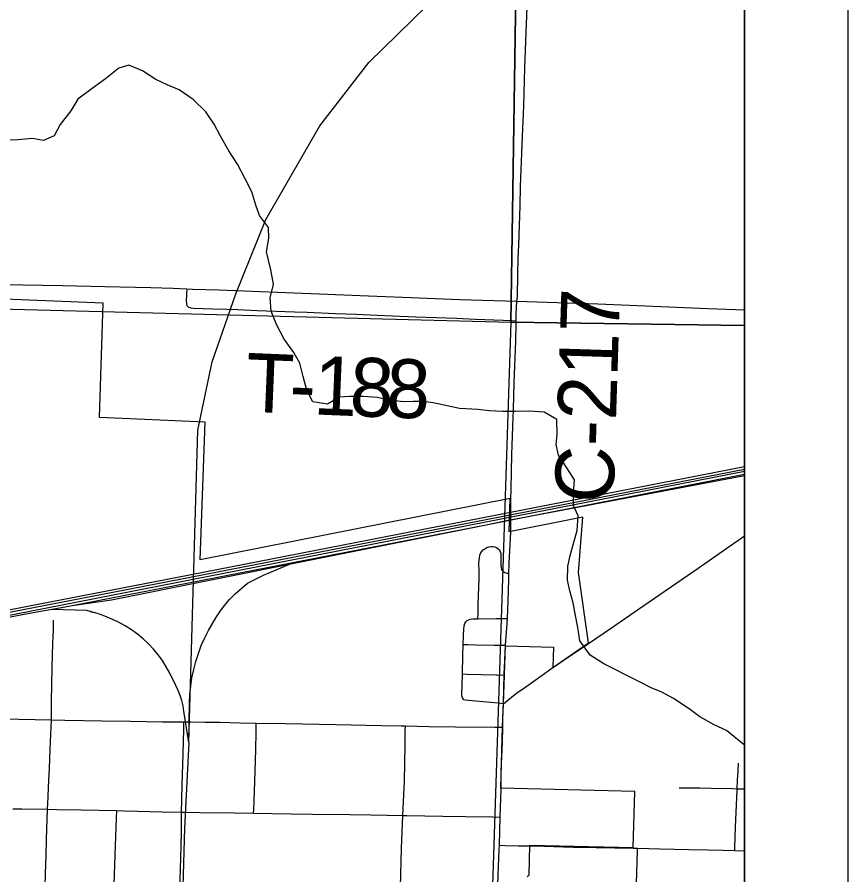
# Model space of a CAD drawing. Extents: x 0 to 34, y 0 to 22.
# Drawn here: x 8.197 to 9, y 19.899 to 20.728 of the extents above; entities that cross this region are included whole.
import ezdxf

# ---------------------------------------------------------------- set-up
doc = ezdxf.new("R2010")
doc.units = 0
for name, color, linetype in [('GM_X_City_Street', 7, 'Continuous'), ('GM_X_County_Road', 7, 'Continuous'), ('GM_X_County_Road_Text', 7, 'Continuous'), ('GM_X_County_Text', 7, 'Continuous'), ('GM_X_Minor_River', 7, 'Continuous'), ('GM_X_Rail_Line', 7, 'Continuous'), ('GM_X_Rail_Line_Text', 7, 'Continuous'), ('GM_X_Section', 7, 'Continuous'), ('GM_X_Township_Road', 7, 'Continuous'), ('GM_X_Township_Road_Text', 7, 'Continuous'), ('GM_X_US_Route', 7, 'Continuous'), ('SH_Cut_Line', 7, 'Continuous'), ('SH_Data', 7, 'Continuous')]:
    doc.layers.add(name, color=color, linetype=linetype)

msp = doc.modelspace()

# ---------------------------------------------------------------- linework, layer by layer
at = {"layer": 'GM_X_City_Street'}
for points in [[(8.64212, 20.14621), (8.64232, 20.15123), (8.6426, 20.16086), (8.64274, 20.16808), (8.64301, 20.17744), (8.64329, 20.18466), (8.64328, 20.19188), (8.64324, 20.20013), (8.64361, 20.20509), (8.6441, 20.20752), (8.64477, 20.20926), (8.64571, 20.21086), (8.64734, 20.21274), (8.64879, 20.21392), (8.65096, 20.21512), (8.65273, 20.21572), (8.65457, 20.21603), (8.65643, 20.21601), (8.65827, 20.21567), (8.66002, 20.21502), (8.66159, 20.21402), (8.66288, 20.2127), (8.6638, 20.21109), (8.6643, 20.2093), (8.6645, 20.20682), (8.66436, 20.19811), (8.66458, 20.19562), (8.66512, 20.19385), (8.66575, 20.19279), (8.66663, 20.19192), (8.66821, 20.19095), (8.66939, 20.19055), (8.67225, 20.18956)], [(8.22324, 19.87397), (8.2233, 19.87608), (8.22365, 19.88895), (8.22428, 19.90943), (8.22453, 19.91739), (8.22507, 19.93283), (8.22607, 19.9621), (8.22649, 19.97365), (8.22699, 19.98356), (8.22745, 19.99596), (8.22777, 20.00153), (8.22865, 20.02013), (8.22973, 20.04859), (8.22971, 20.05429), (8.22987, 20.06645), (8.23011, 20.08202), (8.23043, 20.09898), (8.23119, 20.12256), (8.23156, 20.1356), (8.23173, 20.14494)], [(8.62801, 20.12131), (8.62827, 20.12994), (8.62853, 20.13615), (8.62897, 20.13923), (8.62969, 20.14161), (8.63059, 20.14323), (8.63188, 20.14455), (8.63294, 20.14519), (8.6347, 20.14577), (8.63717, 20.14602), (8.64212, 20.14621)], [(8.64212, 20.14621), (8.65975, 20.14657), (8.66825, 20.14658), (8.67077, 20.14658)], [(8.62724, 20.09287), (8.62771, 20.11071), (8.62801, 20.12131)], [(8.62801, 20.12131), (8.63276, 20.12123), (8.64015, 20.1211), (8.65793, 20.12078), (8.66898, 20.12051)], [(8.66688, 20.0641), (8.66199, 20.06456), (8.65457, 20.06525), (8.63974, 20.06661), (8.62982, 20.06747), (8.62869, 20.06791), (8.6278, 20.06875), (8.62717, 20.06982), (8.62664, 20.0716), (8.62654, 20.07346), (8.62722, 20.09208), (8.62724, 20.09287)], [(8.62724, 20.09287), (8.63148, 20.09274), (8.65955, 20.09192), (8.66079, 20.0919), (8.66778, 20.09181)], [(8.17433, 20.04953), (8.19826, 20.04916), (8.21409, 20.04892), (8.22973, 20.04859), (8.24268, 20.04833), (8.27872, 20.04753), (8.30607, 20.04718), (8.33713, 20.04668), (8.35783, 20.04655), (8.36458, 20.04651), (8.37802, 20.04634), (8.39268, 20.04609), (8.41223, 20.04575), (8.42784, 20.04543), (8.45583, 20.04485), (8.47259, 20.04447), (8.50472, 20.044), (8.54904, 20.04311), (8.56809, 20.04265), (8.57206, 20.04258), (8.59471, 20.04216), (8.62049, 20.04178), (8.65841, 20.04139), (8.66621, 20.04131)], [(8.34791, 19.69227), (8.3487, 19.70216), (8.34925, 19.71894), (8.34964, 19.74527), (8.35001, 19.76184), (8.35037, 19.77266), (8.35054, 19.77794), (8.3508, 19.78364), (8.35105, 19.79045), (8.35169, 19.80899), (8.35285, 19.84255), (8.35348, 19.86309), (8.35361, 19.87148), (8.35368, 19.87533), (8.3541, 19.89351), (8.35509, 19.92644), (8.35543, 19.94011), (8.3556, 19.95915), (8.35592, 19.97146), (8.35625, 19.98574), (8.35716, 20.01534), (8.3574, 20.02845), (8.35765, 20.03857), (8.35783, 20.04655)], [(8.42525, 19.95827), (8.42535, 19.96122), (8.42564, 19.97032), (8.42653, 19.98897), (8.42744, 20.01944), (8.42771, 20.03686), (8.42784, 20.04543)], [(8.56466, 19.78016), (8.56472, 19.78194), (8.56625, 19.82638), (8.56662, 19.84442), (8.56674, 19.86798), (8.56686, 19.87176), (8.56721, 19.88673), (8.56836, 19.92405), (8.56957, 19.95607), (8.57002, 19.96278), (8.57104, 19.98934), (8.57174, 20.02357), (8.57193, 20.03177), (8.572, 20.03787), (8.57206, 20.04258)], [(8.19223, 19.96259), (8.20123, 19.96252), (8.22607, 19.9621), (8.2348, 19.96194), (8.25843, 19.96156), (8.29293, 19.96077), (8.30003, 19.9605), (8.31309, 19.96006), (8.33672, 19.95947), (8.3556, 19.95915), (8.35911, 19.9591), (8.3734, 19.95901), (8.40635, 19.95855), (8.42525, 19.95827), (8.46168, 19.95774), (8.48219, 19.95743), (8.51825, 19.95693), (8.53876, 19.95653), (8.5543, 19.95636), (8.56957, 19.95607), (8.57356, 19.956), (8.60838, 19.95536), (8.63027, 19.95503), (8.65625, 19.95457), (8.6637, 19.95444)], [(8.29025, 19.88978), (8.29123, 19.91778), (8.29187, 19.93572), (8.29261, 19.95311), (8.29293, 19.96077)]]:
    msp.add_lwpolyline(points, dxfattribs=at)
at = {"layer": 'GM_X_County_Road'}
for p, q in [((8.66778, 20.09181), (8.66898, 20.12051)), ((8.66688, 20.0641), (8.66778, 20.09181)), ((8.6637, 19.95444), (8.66455, 19.98183))]:
    msp.add_line(p, q, dxfattribs=at)
for points in [[(8.67991, 20.45306), (8.68024, 20.45562), (8.68039, 20.458), (8.68076, 20.47941), (8.68124, 20.4947), (8.68173, 20.50739), (8.68319, 20.54527), (8.68351, 20.56391), (8.68547, 20.61237), (8.68649, 20.64218), (8.68756, 20.67884), (8.68881, 20.71302), (8.69112, 20.77015), (8.69174, 20.7893)], [(8.67927, 20.43427), (8.67936, 20.44071), (8.67991, 20.45306)], [(8.6741, 20.26174), (8.67426, 20.27169), (8.675, 20.30459), (8.67609, 20.33191), (8.67661, 20.3487), (8.6773, 20.37418), (8.67885, 20.41456), (8.67922, 20.43134), (8.67927, 20.43427)], [(8.67389, 20.22988), (8.67399, 20.23696), (8.67412, 20.24786), (8.6741, 20.26174)], [(8.67077, 20.14658), (8.67144, 20.16344), (8.67207, 20.18393), (8.67225, 20.18956), (8.67259, 20.20007), (8.67389, 20.22988)], [(8.74911, 20.12236), (8.77135, 20.13754), (8.79748, 20.15542), (8.8551, 20.19525), (8.9, 20.22644)], [(8.66898, 20.12051), (8.67057, 20.14168), (8.67077, 20.14658)], [(8.71478, 20.09899), (8.71904, 20.10193), (8.72481, 20.1057), (8.74911, 20.12236)], [(8.66688, 20.0641), (8.67475, 20.0705), (8.67996, 20.07454), (8.68625, 20.07867), (8.70195, 20.08998), (8.71478, 20.09899)], [(8.66621, 20.04131), (8.6664, 20.04923), (8.66688, 20.0641)], [(8.66455, 19.98183), (8.66483, 19.99899), (8.66587, 20.0269), (8.66621, 20.04131)], [(8.66295, 19.92722), (8.66329, 19.94135), (8.6637, 19.95444)], [(8.66084, 19.86631), (8.66093, 19.86925), (8.66189, 19.89846), (8.66284, 19.92269), (8.66295, 19.92722)]]:
    msp.add_lwpolyline(points, dxfattribs=at)
at = {"layer": 'GM_X_County_Text'}
msp.add_lwpolyline([(8.9, 16.39809), (8.9, 20.9)], dxfattribs=at)
at = {"layer": 'GM_X_Minor_River'}
for points in [[(8.22201, 20.60842), (8.21143, 20.61052), (8.19738, 20.60928), (8.18409, 20.60878), (8.17089, 20.61245), (8.16078, 20.6191), (8.14767, 20.62732), (8.13418, 20.63556), (8.12443, 20.64144), (8.10754, 20.6505), (8.09664, 20.65564), (8.08237, 20.66275), (8.06926, 20.67136), (8.06987, 20.68311), (8.07771, 20.69624), (8.08131, 20.70604), (8.07927, 20.71822), (8.06573, 20.72418), (8.05626, 20.72436), (8.04143, 20.72238), (8.03115, 20.72068), (8.02134, 20.72277), (8.01362, 20.73544)], [(8.9, 20.02391), (8.89827, 20.02527), (8.88259, 20.03809), (8.87056, 20.04364), (8.85668, 20.0515), (8.84659, 20.05928), (8.83123, 20.06907), (8.81998, 20.07536), (8.80982, 20.07935), (8.79968, 20.08448), (8.78615, 20.0912), (8.77377, 20.09789), (8.764, 20.10263), (8.75089, 20.11085), (8.74092, 20.12471), (8.73889, 20.13765), (8.73612, 20.15099), (8.73443, 20.16165), (8.73123, 20.1731), (8.72878, 20.18339), (8.72904, 20.19667), (8.73151, 20.20725), (8.73477, 20.21895), (8.73805, 20.23141), (8.73908, 20.24581), (8.73473, 20.25577), (8.73457, 20.26716), (8.73558, 20.28042), (8.72822, 20.29195), (8.72011, 20.30425), (8.71804, 20.31454), (8.71899, 20.32439), (8.71851, 20.33882), (8.70613, 20.34589), (8.69212, 20.34692), (8.67846, 20.34642), (8.66595, 20.34667), (8.65307, 20.3473), (8.64247, 20.34864), (8.62429, 20.34937), (8.61258, 20.35188), (8.59898, 20.3548), (8.58915, 20.35612), (8.57967, 20.35631), (8.5698, 20.35574), (8.55656, 20.35752), (8.54486, 20.36002), (8.53122, 20.36104), (8.51795, 20.36092), (8.50846, 20.36034), (8.49657, 20.35374), (8.48259, 20.35591), (8.47673, 20.36703), (8.4732, 20.38038), (8.47004, 20.39335), (8.46417, 20.40371), (8.45493, 20.41641), (8.44724, 20.43061), (8.44219, 20.44361), (8.4413, 20.45653), (8.44459, 20.46975), (8.44182, 20.48346), (8.43761, 20.501), (8.44014, 20.51424), (8.43958, 20.5245), (8.43108, 20.53605), (8.42748, 20.54598), (8.42356, 20.55897), (8.41697, 20.57162), (8.40967, 20.5858), (8.40119, 20.59849), (8.39312, 20.61269), (8.38727, 20.62419), (8.37916, 20.63611), (8.36688, 20.64811), (8.35341, 20.65748), (8.34174, 20.66227), (8.33085, 20.66741), (8.31774, 20.67601), (8.30457, 20.6812), (8.29503, 20.67835), (8.28194, 20.66798), (8.26925, 20.65874), (8.25539, 20.64838), (8.24835, 20.63713), (8.23824, 20.62405), (8.23234, 20.61315), (8.22201, 20.60842)]]:
    msp.add_lwpolyline(points, dxfattribs=at)
at = {"layer": 'GM_X_Rail_Line'}
for p, q in [((7.61088, 20.03642), (8.9, 20.2888)), ((8.9, 20.28559), (8.68727, 20.24405)), ((8.9, 20.28437), (8.68727, 20.24405)), ((8.68727, 20.24405), (8.65031, 20.23683)), ((8.65031, 20.23683), (8.24982, 20.15862)), ((8.26726, 20.15325), (8.27111, 20.15237))]:
    msp.add_line(p, q, dxfattribs=at)
for points in [[(8.36251, 20.02649), (8.37131, 20.32857), (8.38508, 20.39443), (8.40805, 20.46029), (8.43714, 20.53227), (8.4892, 20.62263), (8.53666, 20.6839), (8.60709, 20.75282), (8.68976, 20.8248), (8.77493, 20.9)], [(2.1, 18.95988), (2.57385, 19.05231), (3.12336, 19.16025), (3.67672, 19.26664), (4.26091, 19.38383), (4.9006, 19.50873), (5.49482, 19.62592), (6.09597, 19.74233), (6.71483, 19.86492), (7.2736, 19.97671), (7.84161, 20.08773), (8.28862, 20.17408), (8.36329, 20.18864), (8.9, 20.29327)], [(2.1, 18.95751), (2.5743, 19.05003), (3.12381, 19.15797), (3.67717, 19.26436), (4.26137, 19.38155), (4.90105, 19.50645), (5.49527, 19.62364), (6.09642, 19.74005), (6.71529, 19.86264), (7.27405, 19.97443), (7.84206, 20.08545), (8.28907, 20.1718), (8.36374, 20.18636), (8.9, 20.29091)], [(8.68727, 20.24405), (8.66979, 20.24074), (8.65031, 20.23683)], [(8.65031, 20.23683), (8.47908, 20.20251), (8.28796, 20.16429), (8.24982, 20.15862)], [(8.36251, 20.02649), (8.36328, 20.06481), (8.36365, 20.07293), (8.36445, 20.08102), (8.36567, 20.08906), (8.36731, 20.09702), (8.36936, 20.10489), (8.37182, 20.11263), (8.37469, 20.12024), (8.37794, 20.12769), (8.38159, 20.13496), (8.38502, 20.1411), (8.38867, 20.1471), (8.39255, 20.15297), (8.39712, 20.15907), (8.40207, 20.16488), (8.40736, 20.17037), (8.41942, 20.18075), (8.43487, 20.18832), (8.4592, 20.19854)], [(8.24982, 20.15862), (8.24644, 20.15812), (8.20493, 20.15073), (8.07341, 20.12524), (7.69106, 20.04995)], [(8.36251, 20.02649), (8.35792, 20.05677), (8.35697, 20.06194), (8.3557, 20.06705), (8.35411, 20.07207), (8.3522, 20.07698), (8.35, 20.08176), (8.34413, 20.0935), (8.34076, 20.09972), (8.337, 20.10572), (8.33285, 20.11145), (8.32835, 20.11691), (8.3235, 20.12206), (8.31832, 20.12689), (8.31285, 20.13138), (8.3071, 20.1355), (8.30109, 20.13924), (8.29464, 20.14275), (8.28801, 20.14591), (8.28122, 20.14873), (8.2743, 20.15117), (8.26726, 20.15325), (8.26384, 20.15412), (8.22987, 20.15517)], [(8.36251, 20.02649), (8.35856, 19.94363), (8.34147, 19.34782)]]:
    msp.add_lwpolyline(points, dxfattribs=at)
at = {"layer": 'GM_X_Rail_Line_Text'}
for points in [[(8.68127, 20.9), (7.67137, 20.9), (7.65944, 20.45935), (8.674, 20.43307)], [(8.9, 20.42976), (8.9, 20.9), (8.68127, 20.9), (8.674, 20.43307)], [(8.9, 19.41791), (8.9, 20.42976), (8.674, 20.43307), (8.64101, 19.4232)]]:
    msp.add_lwpolyline(points, close=True, dxfattribs=at)
at = {"layer": 'GM_X_Section'}
msp.add_lwpolyline([(7.65944, 20.45935), (8.674, 20.43307), (8.64101, 19.4232), (7.63985, 19.45485)], close=True, dxfattribs=at)
at = {"layer": 'GM_X_Township_Road'}
for p, q in [((8.89306, 19.98187), (8.9, 19.98168)), ((8.79251, 19.92436), (8.7966, 19.92428)), ((8.89068, 19.92205), (8.9, 19.92179))]:
    msp.add_line(p, q, dxfattribs=at)
for points in [[(7.91339, 20.47292), (7.92634, 20.47246), (7.9451, 20.47218), (8.02075, 20.47119), (8.06454, 20.47077), (8.08436, 20.47052), (8.11612, 20.47035), (8.18271, 20.46942), (8.24057, 20.46835), (8.28137, 20.46747), (8.32579, 20.46651), (8.34755, 20.46576), (8.36071, 20.46515)], [(8.36071, 20.46515), (8.36041, 20.46008), (8.36031, 20.45827), (8.36016, 20.45385), (8.36038, 20.45055), (8.36083, 20.44914)], [(8.36083, 20.44914), (8.36127, 20.44847), (8.36187, 20.44786), (8.36257, 20.44743), (8.36456, 20.44685), (8.36713, 20.4465), (8.38586, 20.44594), (8.39951, 20.44539), (8.41006, 20.44501), (8.42869, 20.44427), (8.46474, 20.4429), (8.47717, 20.44249), (8.50451, 20.44139), (8.52439, 20.44052), (8.5449, 20.43965), (8.58218, 20.43806), (8.62135, 20.43669), (8.63998, 20.43584), (8.6667, 20.43471), (8.67505, 20.43442), (8.67927, 20.43427)], [(8.89306, 19.98187), (8.89342, 19.99014), (8.89385, 19.99892), (8.89419, 20.00667)], [(8.83675, 19.98282), (8.85724, 19.98269), (8.86774, 19.98248), (8.88856, 19.982), (8.89306, 19.98187)], [(8.89068, 19.92205), (8.89076, 19.92469), (8.89143, 19.94485), (8.893, 19.98065), (8.89306, 19.98187)], [(8.66295, 19.92722), (8.66864, 19.92709), (8.68111, 19.92683), (8.69148, 19.9267)], [(8.69148, 19.9267), (8.69242, 19.92669), (8.70617, 19.92633), (8.73418, 19.92553), (8.75652, 19.92498), (8.79251, 19.92436)], [(8.79478, 19.86295), (8.79485, 19.87027), (8.79502, 19.87644), (8.79552, 19.89065), (8.79619, 19.91104), (8.79653, 19.92203), (8.7966, 19.92428)], [(8.7966, 19.92428), (8.81845, 19.92387), (8.84632, 19.92315), (8.86527, 19.92269), (8.87902, 19.92238), (8.89068, 19.92205)]]:
    msp.add_lwpolyline(points, dxfattribs=at)
at = {"layer": 'GM_X_US_Route'}
for points in [[(7.91339, 20.47292), (7.92634, 20.47246), (7.9451, 20.47218), (8.02075, 20.47119), (8.06454, 20.47077), (8.08436, 20.47052), (8.11612, 20.47035), (8.18271, 20.46942), (8.24057, 20.46835), (8.28137, 20.46747), (8.32579, 20.46651), (8.34755, 20.46576), (8.36071, 20.46515)], [(8.36071, 20.46515), (8.36617, 20.4649), (8.39165, 20.46409), (8.48857, 20.46034), (8.53641, 20.45848), (8.56933, 20.45709), (8.62462, 20.45491), (8.67991, 20.45306), (8.75816, 20.45056), (8.86497, 20.44621), (8.9, 20.44479)], [(8.68976, 19.89669), (8.69188, 19.89869), (8.69235, 19.92741), (8.79243, 19.92508), (8.79404, 19.9792), (8.66448, 19.98255), (8.66614, 20.04202), (8.66681, 20.06482), (8.66771, 20.09253), (8.66895, 20.12007), (8.71536, 20.11858), (8.71473, 20.0991), (8.74914, 20.12291), (8.73962, 20.19083), (8.74373, 20.24434), (8.67252, 20.23031), (8.67355, 20.26239), (8.37348, 20.20328), (8.37855, 20.33639), (8.27613, 20.34062), (8.27979, 20.45125), (8.17615, 20.45538)]]:
    msp.add_lwpolyline(points, dxfattribs=at)
at = {"layer": 'SH_Cut_Line'}
msp.add_lwpolyline([(8.9, 16.39809), (8.9, 20.9), (2.1, 20.9)], dxfattribs=at)
at = {"layer": 'SH_Data'}
for p, q in [((9, 21), (9, 14)), ((8.9, 20.9), (8.9, 14.1))]:
    msp.add_line(p, q, dxfattribs=at)

# ---------------------------------------------------------------- texts
at = {"layer": 'GM_X_County_Road_Text'}
msp.add_text('C-217', height=0.056818, rotation=88.17275, dxfattribs=at).set_placement((8.77318, 20.25746))
at = {"layer": 'GM_X_Township_Road_Text'}
for s, rotation, p in [('T', 357.63796, (8.41666, 20.34648)), ('1', 357.66156, (8.48246, 20.34377)), ('8', 357.73102, (8.51751, 20.34234)), ('8', 358.07536, (8.55286, 20.34094)), ('-', 357.64393, (8.45913, 20.34473))]:
    msp.add_text(s, height=0.05682, rotation=rotation, dxfattribs=at).set_placement(p)

doc.saveas('drawing.dxf')
